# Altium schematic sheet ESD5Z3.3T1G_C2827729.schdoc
size 127 x 101 mm
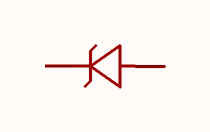
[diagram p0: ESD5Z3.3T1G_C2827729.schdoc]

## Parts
D?  esd5z3.3t1g  [SOD-523_L1.2-W0.8-LS1.6-FD]  (value not drawn)

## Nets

Not connected (* = marked no-connect by the designer): D? 1(A) 2(K)

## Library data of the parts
D? = esd5z3.3t1g: 极性:单向;反向截止电压(Vrwm):3.3V;钳位电压:14V;峰值脉冲电流(Ipp):11A;峰值脉冲功率(Ppp):150W;击穿电压:5V;; Manufacturer: TECH PUBLIC(台舟); Symbol: ESD5Z3.3T1G_C2827729; AddInBom: yes; ModelId: 8f56a03db567494d8f4c9d12aa52a741; ModelName: SOD-523_L1.2-W0.8-H0.7-LS1.6; ModelTransform: 62.992,31.496,0,0,0,0,0,0,0; Polarity: 单向; Reverse Stand-Off Voltage (Vrwm): 3.3V; Clamping Voltage: 14V; Peak Pulse Current (Ipp): 11A; Peak Pulse Power Dissipation (Ppp): 150W; Voltage - Breakdown: 5V; Reverse Leakage Current (Ir): 200nA; Number of Channels: 单路; level of protection: IEC 61000-4-2；IEC 61000-4-4; Type: ESD; Junction Capacitance: 110pF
